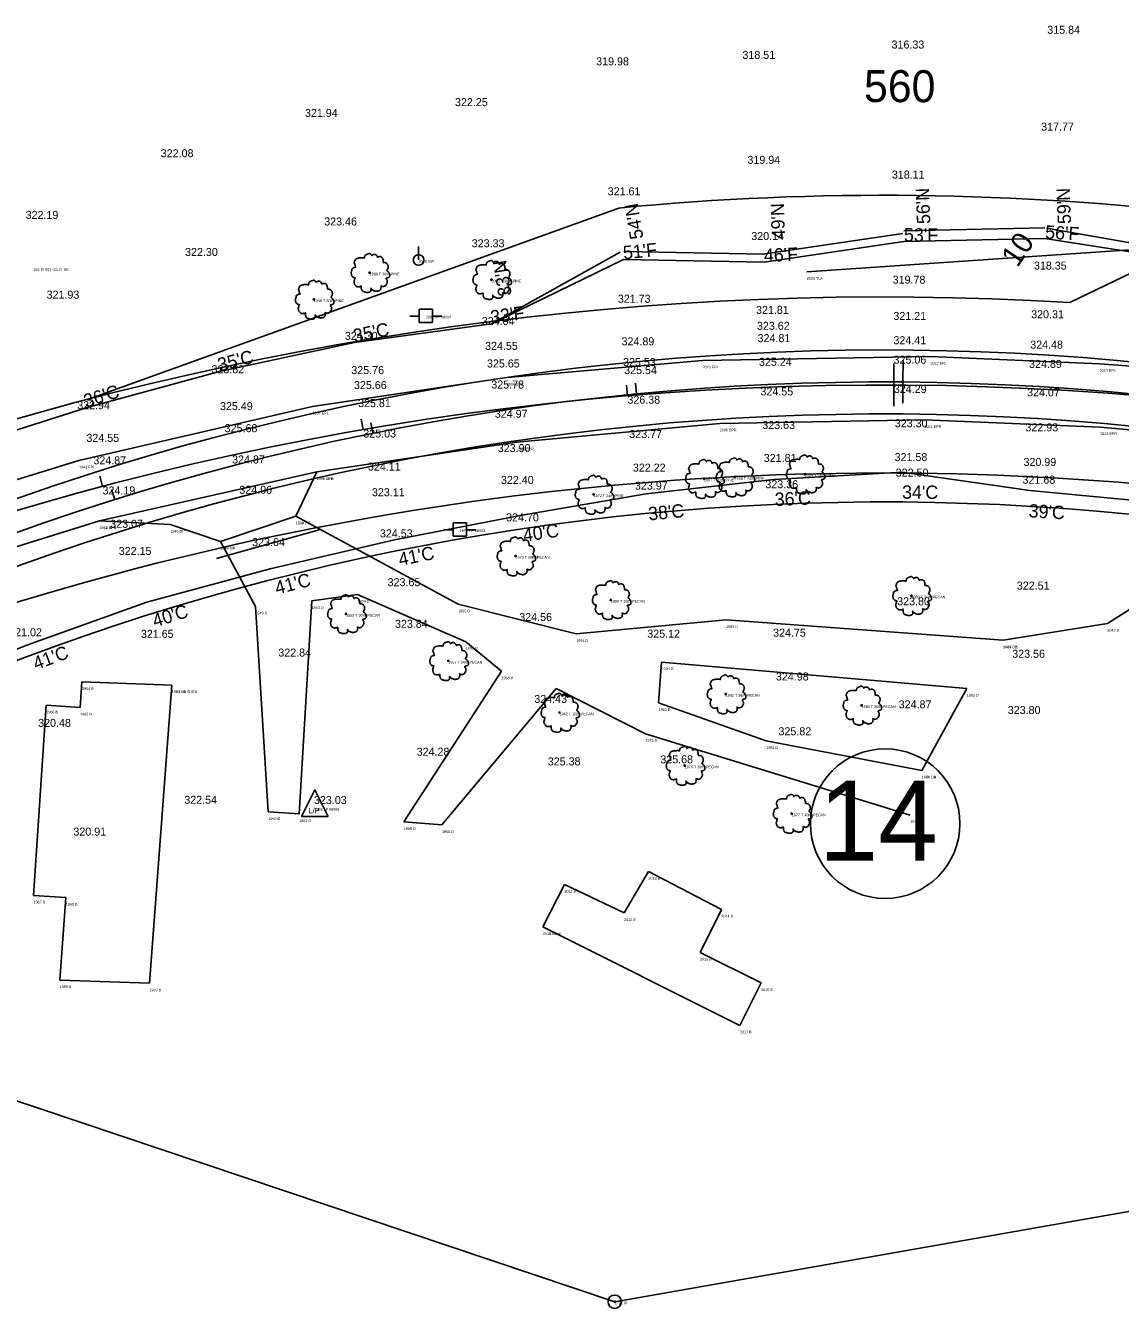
# Model space of a CAD drawing. Extents: x 49683 to 58852, y 49525 to 54803.
# Drawn here: x 56470.1 to 56880.6, y 53724.8 to 54205.8 of the extents above; entities that cross this region are included whole.
import ezdxf

# ---------------------------------------------------------------- set-up
doc = ezdxf.new("R2010")
doc.units = 0
for name, color, linetype in [('Level 1', 7, 'Continuous'), ('Level 11', 7, 'Continuous'), ('Level 12', 7, 'Continuous'), ('Level 13', 7, 'Continuous'), ('Level 18', 7, 'Continuous'), ('Level 19', 7, 'Continuous'), ('Level 20', 7, 'Continuous'), ('Level 21', 7, 'Continuous'), ('Level 25', 7, 'Continuous'), ('Level 3', 7, 'Continuous'), ('Level 32', 7, 'Continuous'), ('Level 33', 7, 'Continuous'), ('Level 34', 7, 'Continuous'), ('Level 48', 7, 'Continuous'), ('Level 51', 7, 'Continuous'), ('Level 53', 7, 'Continuous'), ('Level 58', 7, 'Continuous'), ('Level 59', 7, 'Continuous'), ('Level 61', 7, 'Continuous'), ('Level 62', 7, 'Continuous'), ('Level 8', 7, 'Continuous'), ('Level 9', 7, 'Continuous')]:
    doc.layers.add(name, color=color, linetype=linetype)

# ---------------------------------------------------------------- blocks, each defined once
blk = doc.blocks.new('IP')
at = {"layer": 'Level 12'}
for radius in [2.5, 0.25]:
    blk.add_circle((0, 0), radius, dxfattribs=at)
blk = doc.blocks.new('LP')
at = {"layer": 'Level 9'}
for p, q in [((-4.79, -3.23), (0.21, 6.77)), ((0.21, 6.77), (5.21, -3.23)), ((-4.79, -3.23), (5.21, -3.23))]:
    blk.add_line(p, q, dxfattribs=at)
blk.add_text('L/P', height=2, dxfattribs=at).set_placement((-2.19, -1.95))
blk = doc.blocks.new('T1')
at = {"layer": 'Level 11'}
for centre, radius in [((0, 0), 0.25), ((-0.01, -0.02), 0.0001)]:
    blk.add_circle(centre, radius, dxfattribs=at)
for points in [[(0.13, 7.17), (-0.17, 7.19), (-0.49, 7.09), (-0.74, 6.99), (-0.97, 6.92), (-1.19, 6.82), (-1.49, 6.64), (-1.72, 6.44), (-1.84, 6.19), (-1.89, 5.97), (-1.94, 5.69), (-1.94, 5.52), (-2.07, 5.49), (-2.22, 5.52), (-2.47, 5.59), (-2.72, 5.59), (-2.97, 5.59), (-3.32, 5.57), (-3.67, 5.57), (-3.94, 5.52), (-4.27, 5.47), (-4.64, 5.34), (-4.99, 5.22), (-5.29, 4.97), (-5.54, 4.49), (-5.67, 4.14), (-5.82, 3.89), (-5.67, 3.44), (-5.49, 3.09), (-5.47, 2.89), (-5.39, 2.47), (-5.29, 2.24), (-5.17, 2.04), (-5.24, 2.02), (-5.62, 1.97), (-5.92, 1.87), (-6.34, 1.64), (-6.57, 1.42), (-6.67, 1.09), (-6.69, 0.75), (-6.79, 0.55), (-6.87, 0.27), (-6.89, 0.2), (-6.94, -0.13), (-6.84, -0.58), (-6.82, -0.93), (-6.69, -1.15), (-6.54, -1.33), (-6.37, -1.58), (-5.97, -1.8), (-5.64, -1.9), (-5.44, -1.93), (-5.62, -2.43), (-5.67, -2.78), (-5.79, -3.18), (-5.79, -3.25), (-5.84, -3.73), (-5.69, -4.05), (-5.62, -4.43), (-5.44, -4.65), (-5.17, -4.95), (-4.84, -5.18), (-4.34, -5.3), (-3.94, -5.28), (-3.37, -5.1), (-3.12, -5.03), (-3.14, -5.2), (-3.12, -5.58), (-3.12, -6), (-2.97, -6.33), (-2.87, -6.6), (-2.72, -6.85), (-2.39, -7.08), (-1.99, -7.15), (-1.57, -7.3), (-1.12, -7.38), (-0.62, -7.4), (-0.02, -7.25), (0.26, -7.13), (0.36, -6.95), (0.56, -6.58), (0.51, -6.35), (0.53, -5.75), (0.63, -5.93), (0.81, -6.28), (1.31, -6.58), (1.71, -6.75), (2.18, -6.9), (2.48, -6.98), (2.96, -6.9), (3.33, -6.83), (3.71, -6.7), (4.01, -6.43), (4.18, -6.15), (4.23, -5.88), (4.31, -5.5), (4.36, -5.33)], [(4.36, -5.33), (4.28, -5.15), (4.23, -4.9), (4.31, -4.93), (4.48, -4.98), (4.75, -5.1), (4.98, -5.18), (5.3, -5.15), (5.58, -5.05), (6.03, -4.78), (6.3, -4.3), (6.58, -3.9), (6.65, -3.58), (6.6, -3.35), (6.58, -2.85), (6.38, -2.6), (6.33, -2.48), (6.23, -2.08), (6.3, -2.03), (6.58, -1.98), (6.95, -1.85), (7.23, -1.73), (7.45, -1.55), (7.53, -1.33), (7.5, -0.93), (7.55, -0.53), (7.48, -0.38), (7.38, -0.23), (7.3, -0.03), (7.15, 0.12), (7.05, 0.27), (6.95, 0.37), (6.83, 0.52), (6.65, 0.65), (6.5, 0.7), (6.45, 0.85), (6.6, 1.04), (6.65, 1.14), (6.68, 1.37), (6.9, 1.72), (6.95, 2.12), (6.9, 2.54), (6.85, 2.82), (6.7, 3.09), (6.5, 3.34), (6.38, 3.52), (6.2, 3.64), (5.88, 3.77), (5.63, 3.82), (5.28, 3.82), (5.08, 3.87), (5.1, 3.92), (5.1, 4.07), (5.1, 4.34), (5.03, 4.79), (4.88, 5.29), (4.88, 5.32), (4.78, 5.57), (4.56, 5.77), (4.38, 5.87), (4.18, 5.99), (3.93, 6.02), (3.63, 6.02), (3.36, 5.97), (3.16, 5.87), (2.98, 5.74), (2.91, 5.89), (2.81, 6.19), (2.76, 6.34), (2.61, 6.52), (2.38, 6.72), (1.93, 6.84), (1.31, 6.77), (1.01, 6.57), (0.86, 6.39), (0.81, 6.52), (0.61, 6.72), (0.51, 6.89), (0.33, 7.02), (0.18, 7.12), (0.08, 7.17)]]:
    blk.add_spline(points, degree=3, dxfattribs=at)
blk = doc.blocks.new('PP')
at = {"layer": 'Level 9'}
for p, q in [((2.53, 2.45), (-2.47, 2.45)), ((-2.47, 2.45), (-2.47, -2.55)), ((2.53, -2.55), (2.53, 2.45)), ((-5.91, -0.11), (-2.44, -0.11)), ((-2.47, -2.55), (2.53, -2.55)), ((2.45, -0.11), (6.09, -0.11))]:
    blk.add_line(p, q, dxfattribs=at)
blk = doc.blocks.new('GW')
at = {"layer": 'Level 9'}
blk.add_line((0, 0), (0, 5), dxfattribs=at)
blk.add_circle((0, 0), 2, dxfattribs=at)

msp = doc.modelspace()

# ---------------------------------------------------------------- linework, layer by layer
at = {"layer": 'Level 1'}
for p, q in [((56795.65, 54071.04), (56795.68, 54079.04)), ((56695.76, 54067.02), (56695.43, 54071.01)), ((56795.62, 54063.04), (56795.65, 54071.04)), ((56596.61, 54054.31), (56595.92, 54058.26)), ((56498.93, 54033.01), (56497.91, 54036.88))]:
    msp.add_line(p, q, dxfattribs=at)
msp.add_arc((56791.72, 52925.13), 1145.92, 83.49443, 131.63333, dxfattribs=at)
at = {"layer": 'Level 11'}
msp.add_line((56763.02, 54113.51), (56919.7, 54124.18), dxfattribs=at)
at = {"layer": 'Level 12'}
for p, q in [((56861.63, 54101.97), (56939.44, 54139.39)), ((56690.99, 53727.29), (57289.55, 53832.27)), ((56427.28, 53815.81), (56690.99, 53727.29))]:
    msp.add_line(p, q, dxfattribs=at)
at = {"layer": 'Level 13'}
for radius, start, end in [(1178.92, 86.60044, 131.63335), (1112.92, 83.49442, 108.44495)]:
    msp.add_arc((56791.72, 52925.13), radius, start, end, dxfattribs=at)
at = {"layer": 'Level 18'}
for p, q in [((56746.6, 54120.08), (56799.01, 54127.84)), ((56799.37, 54128.87), (56852.23, 54129.96)), ((56852.93, 54129.91), (56906.44, 54120.5)), ((56747.04, 54117.11), (56799.45, 54124.87)), ((56799.45, 54124.87), (56852.31, 54125.96)), ((56852.31, 54125.96), (56904.59, 54117.78)), ((56644.77, 54093.92), (56693.02, 54120.85)), ((56644.77, 54093.92), (56694.34, 54118.16)), ((56694.34, 54118.16), (56747.04, 54117.11)), ((56694.4, 54121.16), (56747.1, 54120.11)), ((56593.46, 54086.96), (56644.77, 54093.92)), ((56542.81, 54076.06), (56593.46, 54086.96)), ((56492.76, 54062.49), (56542.81, 54076.06)), ((56443.3, 54046.77), (56492.76, 54062.49)), ((56702.83, 54030.17), (56750.66, 54035.63)), ((56750.66, 54035.63), (56798.81, 54038.41)), ((56798.81, 54038.41), (56846.71, 54031.43)), ((56655.48, 54022.09), (56702.83, 54030.17)), ((56846.71, 54031.43), (56894.46, 54026.92)), ((56608.46, 54012.92), (56655.48, 54022.09)), ((56561.82, 54002.1), (56608.46, 54012.92)), ((56515.58, 53989.64), (56561.82, 54002.1)), ((56470.5, 53973.46), (56515.58, 53989.64)), ((56426.1, 53955.57), (56470.5, 53973.46))]:
    msp.add_line(p, q, dxfattribs=at)
at = {"layer": 'Level 19'}
for p, q in [((56799.06, 54072.17), (56799.12, 54080.17)), ((56699.21, 54067.73), (56698.82, 54071.71)), ((56799.06, 54072.17), (56799, 54064.17)), ((56600.34, 54052.98), (56599.55, 54056.9)), ((56503.54, 54028.08), (56502.34, 54031.9))]:
    msp.add_line(p, q, dxfattribs=at)
msp.add_arc((56791.96, 53107.19), 965, 83.49443, 131.63337, dxfattribs=at)
at = {"layer": 'Level 20'}
for radius, start, end in [(977, 84.11358, 131.63331), (953, 83.49443, 131.63337)]:
    msp.add_arc((56791.96, 53107.19), radius, start, end, dxfattribs=at)
at = {"layer": 'Level 25'}
msp.add_circle((56792.42, 53906.55), 28.04, dxfattribs=at)
at = {"layer": 'Level 3'}
for p, q in [((56650.48, 54073.81), (56723.9, 54080.24)), ((56723.9, 54080.24), (56809.36, 54081.7)), ((56809.36, 54081.7), (56872.82, 54079.01)), ((56872.82, 54079.01), (56910.53, 54076.11)), ((56577.69, 54063.01), (56650.48, 54073.81)), ((56490.09, 54042.73), (56577.69, 54063.01)), ((56654.29, 54049.54), (56730.36, 54056.66)), ((56730.36, 54056.66), (56807.13, 54057.96)), ((56807.13, 54057.96), (56873.04, 54055.26)), ((56873.04, 54055.26), (56924.01, 54050.53)), ((56579.24, 54038.47), (56654.29, 54049.54)), ((56414.45, 54019.29), (56490.09, 54042.73)), ((56497.78, 54020.06), (56579.24, 54038.47)), ((56420.81, 53996.17), (56497.78, 54020.06))]:
    msp.add_line(p, q, dxfattribs=at)
at = {"layer": 'Level 33'}
msp.add_line((56493.7, 54065.76), (56692.48, 54137.4), dxfattribs=at)
for radius, start, end in [(1035, 83.12795, 95.51566), (920, 83.49443, 131.63337)]:
    msp.add_arc((56791.96, 53107.19), radius, start, end, dxfattribs=at)
at = {"layer": 'Level 34'}
msp.add_line((56580.19, 54016.72), (56541.65, 54005.99), dxfattribs=at)
at = {"layer": 'Level 8'}
for p, q in [((56571.37, 54021.8), (56579.24, 54038.47)), ((56543.14, 54012.37), (56571.37, 54021.8)), ((56632.32, 53988.82), (56571.37, 54021.8)), ((56497.78, 54020.06), (56524.35, 54018.72)), ((56524.35, 54018.72), (56543.14, 54012.37)), ((56543.14, 54012.37), (56556.26, 53988.01)), ((56899.53, 53996.66), (56875.73, 53981.59)), ((56577.39, 53990.09), (56594.57, 53992.46)), ((56594.57, 53992.46), (56635.17, 53974.75)), ((56556.26, 53988.01), (56561.1, 53910.97)), ((56572.68, 53910.19), (56577.39, 53990.09)), ((56676.58, 53977.7), (56632.32, 53988.82)), ((56732.77, 53982.97), (56676.58, 53977.7)), ((56836.65, 53975.32), (56732.77, 53982.97)), ((56875.73, 53981.59), (56836.65, 53975.32)), ((56635.17, 53974.75), (56648.5, 53963.72)), ((56648.5, 53963.72), (56611.93, 53907.19)), ((56707.47, 53951.83), (56708.57, 53967.14)), ((56708.57, 53967.14), (56823.01, 53957.2)), ((56491.23, 53959.69), (56490.52, 53950.11)), ((56524.93, 53958.52), (56491.23, 53959.69)), ((56516.55, 53846.72), (56524.93, 53958.52)), ((56626.22, 53906.07), (56669.07, 53957.29)), ((56669.07, 53957.29), (56702.53, 53940.27)), ((56823.01, 53957.2), (56806.15, 53926.5)), ((56477.85, 53950.96), (56473.05, 53879.64)), ((56490.52, 53950.11), (56477.85, 53950.96)), ((56747.83, 53937.57), (56707.47, 53951.83)), ((56702.53, 53940.27), (56801.83, 53909.79)), ((56806.15, 53926.5), (56747.83, 53937.57)), ((56561.1, 53910.97), (56572.68, 53910.19)), ((56611.93, 53907.19), (56626.22, 53906.07)), ((56694.51, 53873.08), (56703.69, 53888.59)), ((56703.69, 53888.59), (56730.98, 53874.36)), ((56664.09, 53867.85), (56672.11, 53883.72)), ((56672.11, 53883.72), (56694.51, 53873.08)), ((56473.05, 53879.64), (56485.18, 53878.82)), ((56485.18, 53878.82), (56482.86, 53847.89)), ((56730.98, 53874.36), (56722.98, 53858.23)), ((56737.97, 53830.92), (56664.09, 53867.85)), ((56722.98, 53858.23), (56745.89, 53846.83)), ((56482.86, 53847.89), (56516.55, 53846.72)), ((56745.89, 53846.83), (56737.97, 53830.92))]:
    msp.add_line(p, q, dxfattribs=at)

# ---------------------------------------------------------------- block references
at = {"layer": 'Level 11'}
for p in [(56599.09, 54113.16), (56644.76, 54110.52), (56578.18, 54103.12), (56762.31, 54037.59), (56724.52, 54035.91), (56735.97, 54036.49), (56683.1, 54030), (56653.82, 54006.87), (56689.55, 53990.45), (56802.24, 53992.01), (56590.28, 53985.2), (56628.59, 53967.6), (56732.63, 53955.14), (56783.57, 53950.92), (56670.3, 53948.23), (56717.25, 53928.33), (56757.4, 53910.32)]:
    msp.add_blockref('T1', p, dxfattribs=at)
at = {"layer": 'Level 12'}
msp.add_blockref('IP', (56690.99, 53727.29), dxfattribs=at)
at = {"layer": 'Level 9'}
for name, p in [('GW', (56617.45, 54117.92)), ('PP', (56620.12, 54097.01)), ('PP', (56632.83, 54016.9)), ('LP', (56578.36, 53912.4))]:
    msp.add_blockref(name, p, dxfattribs=at)

# ---------------------------------------------------------------- texts
at = {"layer": 'Level 21'}
for s, height, rotation, p in [('560', 12, 359.8036, (56784.46, 54177.15)), ('10', 8, 55.9793, (56842.03, 54114.84))]:
    msp.add_text(s, height=height, rotation=rotation, dxfattribs=at).set_placement(p)
at = {"layer": 'Level 25'}
msp.add_text('14', height=30, dxfattribs=at).set_placement((56767.49, 53892.67))
at = {"layer": 'Level 32'}
for s, p in [('315.84', (56853.2, 54202.74)), ('316.33', (56794.81, 54197.21)), ('319.98', (56684.05, 54190.91)), ('318.51', (56738.89, 54193.33)), ('321.94', (56574.84, 54171.56)), ('322.25', (56631.11, 54175.61)), ('317.77', (56850.91, 54166.43)), ('322.08', (56520.77, 54156.45)), ('319.94', (56740.77, 54153.97)), ('318.11', (56794.92, 54148.46)), ('321.61', (56688.36, 54142.16)), ('322.19', (56470.1, 54133.32)), ('323.46', (56582.07, 54130.86)), ('320.14', (56742.21, 54125.4)), ('322.30', (56529.88, 54119.42)), ('323.33', (56637.39, 54122.69)), ('318.35', (56848.2, 54114.32)), ('319.78', (56795.22, 54109.03)), ('321.93', (56477.96, 54103.41)), ('321.73', (56692.17, 54101.88)), ('321.81', (56743.99, 54097.7)), ('321.21', (56795.5, 54095.44)), ('320.31', (56847.15, 54096.06)), ('324.04', (56641.14, 54093.53)), ('323.62', (56744.33, 54091.73)), ('324.30', (56589.81, 54087.97)), ('324.89', (56693.57, 54085.92)), ('324.81', (56744.58, 54087.12)), ('324.41', (56795.52, 54086.33)), ('324.55', (56642.39, 54084.22)), ('324.48', (56846.81, 54084.68)), ('323.82', (56539.8, 54075.46)), ('325.65', (56643.1, 54077.61)), ('325.53', (56694.13, 54078.12)), ('325.24', (56745.09, 54078.23)), ('325.06', (56795.56, 54079.04)), ('324.89', (56846.38, 54077.45)), ('325.76', (56592.22, 54075.12)), ('325.54', (56694.54, 54075.14)), ('325.66', (56593.23, 54069.52)), ('325.78', (56644.72, 54069.72)), ('324.55', (56745.65, 54067.13)), ('324.29', (56795.66, 54068.04)), ('324.07', (56845.64, 54066.78)), ('322.94', (56489.45, 54061.97)), ('325.49', (56542.98, 54061.62)), ('325.81', (56594.76, 54062.75)), ('326.38', (56695.75, 54064.02)), ('324.97', (56646.03, 54058.75)), ('325.68', (56544.74, 54053.35)), ('325.03', (56596.72, 54051.35)), ('323.77', (56696.46, 54051.15)), ('323.63', (56746.34, 54054.55)), ('323.30', (56796.03, 54055.2)), ('322.93', (56845.01, 54053.67)), ('324.55', (56492.89, 54049.71)), ('324.87', (56547.53, 54041.61)), ('323.90', (56647.15, 54045.87)), ('321.81', (56746.89, 54042.18)), ('321.58', (56795.95, 54042.51)), ('324.87', (56495.5, 54041.28)), ('324.11', (56598.47, 54038.95)), ('322.22', (56697.81, 54038.56)), ('320.99', (56844.29, 54040.67)), ('322.40', (56648.34, 54033.94)), ('323.36', (56747.48, 54032.33)), ('322.50', (56796.38, 54036.69)), ('321.68', (56843.91, 54034.01)), ('324.19', (56498.93, 54030.01)), ('324.06', (56550.24, 54030.24)), ('323.11', (56599.96, 54029.33)), ('323.97', (56698.59, 54031.81)), ('323.07', (56501.82, 54017.48)), ('324.70', (56650.28, 54019.9)), ('324.53', (56602.95, 54013.89)), ('323.64', (56555.04, 54010.63)), ('322.15', (56505.01, 54007.31)), ('323.65', (56605.84, 53995.6)), ('322.51', (56841.79, 53994.32)), ('323.80', (56796.93, 53988.44)), ('323.84', (56608.61, 53979.99)), ('324.56', (56655.2, 53982.54)), ('321.02', (56463.93, 53976.82)), ('321.65', (56513.32, 53976.23)), ('325.12', (56703.21, 53976.29)), ('324.75', (56750.38, 53976.66)), ('322.84', (56564.86, 53969.21)), ('323.56', (56840.06, 53968.75)), ('324.98', (56751.46, 53960.24)), ('324.43', (56660.84, 53951.82)), ('324.87', (56797.49, 53949.78)), ('323.80', (56838.39, 53947.66)), ('320.48', (56474.79, 53942.83)), ('325.82', (56752.41, 53939.69)), ('324.28', (56616.73, 53932.02)), ('325.38', (56665.9, 53928.38)), ('325.68', (56708.09, 53929.17)), ('322.54', (56529.59, 53914)), ('323.03', (56578.22, 53913.91)), ('320.91', (56488.01, 53902.07))]:
    msp.add_text(s, height=3, dxfattribs=at).set_placement(p)
at = {"layer": 'Level 48'}
for s, rotation, p in [("56'N", 92.1896, (56809.35, 54131.5)), ("59'N", 92.1896, (56862.14, 54131.5)), ("54'N", 99.3793, (56701.77, 54126.12)), ("49'N", 92.1896, (56754.91, 54125.79)), ("53'F", 359.5783, (56799.45, 54124.87)), ("56'F", 356.6096, (56852.31, 54125.96)), ("51'F", 5.5156, (56694.34, 54118.16)), ("46'F", 2.547, (56747.04, 54117.11)), ("33'N", 99.3793, (56652.41, 54104.79)), ("33'F", 8.4843, (56644.77, 54093.92)), ("35'C", 11.4531, (56593.46, 54086.96)), ("35'C", 14.4218, (56542.81, 54076.06)), ("36'C", 17.3904, (56492.76, 54062.49)), ("36'C", 2.547, (56751.1, 54025.64)), ("34'C", 359.5783, (56798.74, 54028.41)), ("38'C", 5.5157, (56703.79, 54020.22)), ("39'C", 356.6096, (56846.12, 54021.44)), ("40'C", 8.4843, (56656.96, 54012.2)), ("41'C", 11.4531, (56610.44, 54003.12)), ("41'C", 14.4217, (56564.31, 53992.42)), ("40'C", 17.3904, (56518.57, 53980.09)), ("41'C", 20.3591, (56473.98, 53964.08))]:
    msp.add_text(s, height=5, rotation=rotation, dxfattribs=at).set_placement(p)
at = {"layer": 'Level 51'}
msp.add_text('182 PI 557+22.74 RE ', height=1, dxfattribs=at).set_placement((56473.02, 54113.82))
at = {"layer": 'Level 53'}
for s, p in [('2019 EPL ', (56723.9, 54077.24)), ('2022 EPL ', (56809.36, 54078.7)), ('2024 EPL ', (56872.82, 54076.01)), ('2004 EPL ', (56650.48, 54070.81)), ('1997 EPL ', (56577.69, 54060.01)), ('2006 EPR ', (56730.36, 54053.66)), ('2021 EPR ', (56807.13, 54054.96)), ('2023 EPR ', (56873.04, 54052.26)), ('2005 EPR ', (56654.29, 54046.54)), ('1943 EPL ', (56490.09, 54039.73)), ('1996 EPR ', (56579.24, 54035.47)), ('1944 EPR ', (56497.78, 54017.06))]:
    msp.add_text(s, height=1, dxfattribs=at).set_placement(p)
at = {"layer": 'Level 58'}
for s, p in [('1995 DPB ', (56579.24, 54035.47)), ('1945 DPA ', (56497.78, 54017.06)), ('1946 DP ', (56524.35, 54015.72)), ('1993 DB ', (56571.37, 54018.8)), ('1994 DP ', (56571.37, 54018.8)), ('1948 DA ', (56543.14, 54009.37)), ('1947 DP ', (56543.14, 54009.37)), ('1953 D ', (56577.39, 53987.09)), ('1954 D ', (56594.57, 53989.46)), ('1992 D ', (56632.32, 53985.82)), ('1949 D ', (56556.26, 53985.01)), ('1989 D ', (56732.77, 53979.97)), ('2043 D ', (56875.73, 53978.59)), ('1956 D ', (56635.17, 53971.75)), ('1991 D ', (56676.58, 53974.7)), ('2044 DB ', (56836.65, 53972.32)), ('1987 DA ', (56836.65, 53972.32)), ('1984 D ', (56708.57, 53964.14)), ('1958 D ', (56648.5, 53960.72)), ('1964 B ', (56491.23, 53956.69)), ('1963 BA SHED ', (56524.93, 53955.52)), ('1971 BB ', (56524.93, 53955.52)), ('1961 D ', (56669.07, 53954.29)), ('1985 D ', (56823.01, 53954.2)), ('1966 B ', (56477.85, 53947.96)), ('1983 D ', (56707.47, 53948.83)), ('1965 B ', (56490.52, 53947.11)), ('1975 D ', (56702.53, 53937.27)), ('1981 D ', (56747.83, 53934.57)), ('1979 DA ', (56806.15, 53923.5)), ('1986 DB ', (56806.15, 53923.5)), ('1950 D ', (56561.1, 53907.97)), ('1951 D ', (56572.68, 53907.19)), ('1959 D ', (56611.93, 53904.19)), ('1978 DB ', (56801.83, 53906.79)), ('1960 D ', (56626.22, 53903.07)), ('2013 B ', (56703.69, 53885.59)), ('2011 B ', (56672.11, 53880.72)), ('1967 B ', (56473.05, 53876.64)), ('1968 B ', (56485.18, 53875.82)), ('2014 B ', (56730.98, 53871.36)), ('2012 B ', (56694.51, 53870.08)), ('2010 BA R ', (56664.09, 53864.85)), ('2018 BB ', (56664.09, 53864.85)), ('2015 B ', (56722.98, 53855.23)), ('1969 B ', (56482.86, 53844.89)), ('1970 B ', (56516.55, 53843.72)), ('2016 B ', (56745.89, 53843.83)), ('2017 B ', (56737.97, 53827.92))]:
    msp.add_text(s, height=1, dxfattribs=at).set_placement(p)
at = {"layer": 'Level 59'}
for s, p in [('2000 GW ', (56617.45, 54116.92)), ('2001 PP 08904 ', (56620.12, 54096.01)), ('1974 PP 08903 ', (56632.83, 54015.9)), ('1952 LP 08906 ', (56578.36, 53911.4))]:
    msp.add_text(s, height=1, dxfattribs=at).set_placement(p)
at = {"layer": 'Level 61'}
for s, p in [('1999 T 30IN PINE ', (56599.09, 54112.16)), ('2003 T 30IN PINE ', (56644.76, 54109.52)), ('2020 TLA ', (56763.02, 54110.51)), ('1998 T 30IN PINE ', (56578.18, 54102.12)), ('2007 T 30IN PINE ', (56724.52, 54034.91)), ('2008 T 24IN PINE ', (56735.97, 54035.49)), ('2009 T 24IN PINE ', (56762.31, 54036.59)), ('1972 T 24IN PINE ', (56683.1, 54029)), ('1973 T 30IN PECAN ', (56653.82, 54005.87)), ('1988 T 24IN PECAN ', (56802.24, 53991.01)), ('1990 T 18IN PECAN ', (56689.55, 53989.45)), ('1955 T 30IN PECAN ', (56590.28, 53984.2)), ('1957 T 24IN PECAN ', (56628.59, 53966.6)), ('1982 T 36IN PECAN ', (56732.63, 53954.14)), ('1980 T 36IN PECAN ', (56783.57, 53949.92)), ('1962 T 12IN PECAN ', (56670.3, 53947.23)), ('1976 T 30IN PECAN ', (56717.25, 53927.33)), ('1977 T 40IN PECAN ', (56757.4, 53909.32))]:
    msp.add_text(s, height=1, dxfattribs=at).set_placement(p)
at = {"layer": 'Level 62'}
msp.add_text('1721 IP ', height=1, dxfattribs=at).set_placement((56690.99, 53726.29))

doc.saveas('drawing.dxf')
